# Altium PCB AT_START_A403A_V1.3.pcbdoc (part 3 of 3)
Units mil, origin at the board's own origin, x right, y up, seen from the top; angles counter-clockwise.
Board outline 6370 x 3956 mil, 2 copper layers (Top Layer, Bottom Layer); 182 components, 198 nets, 768 pads, 894 vias.
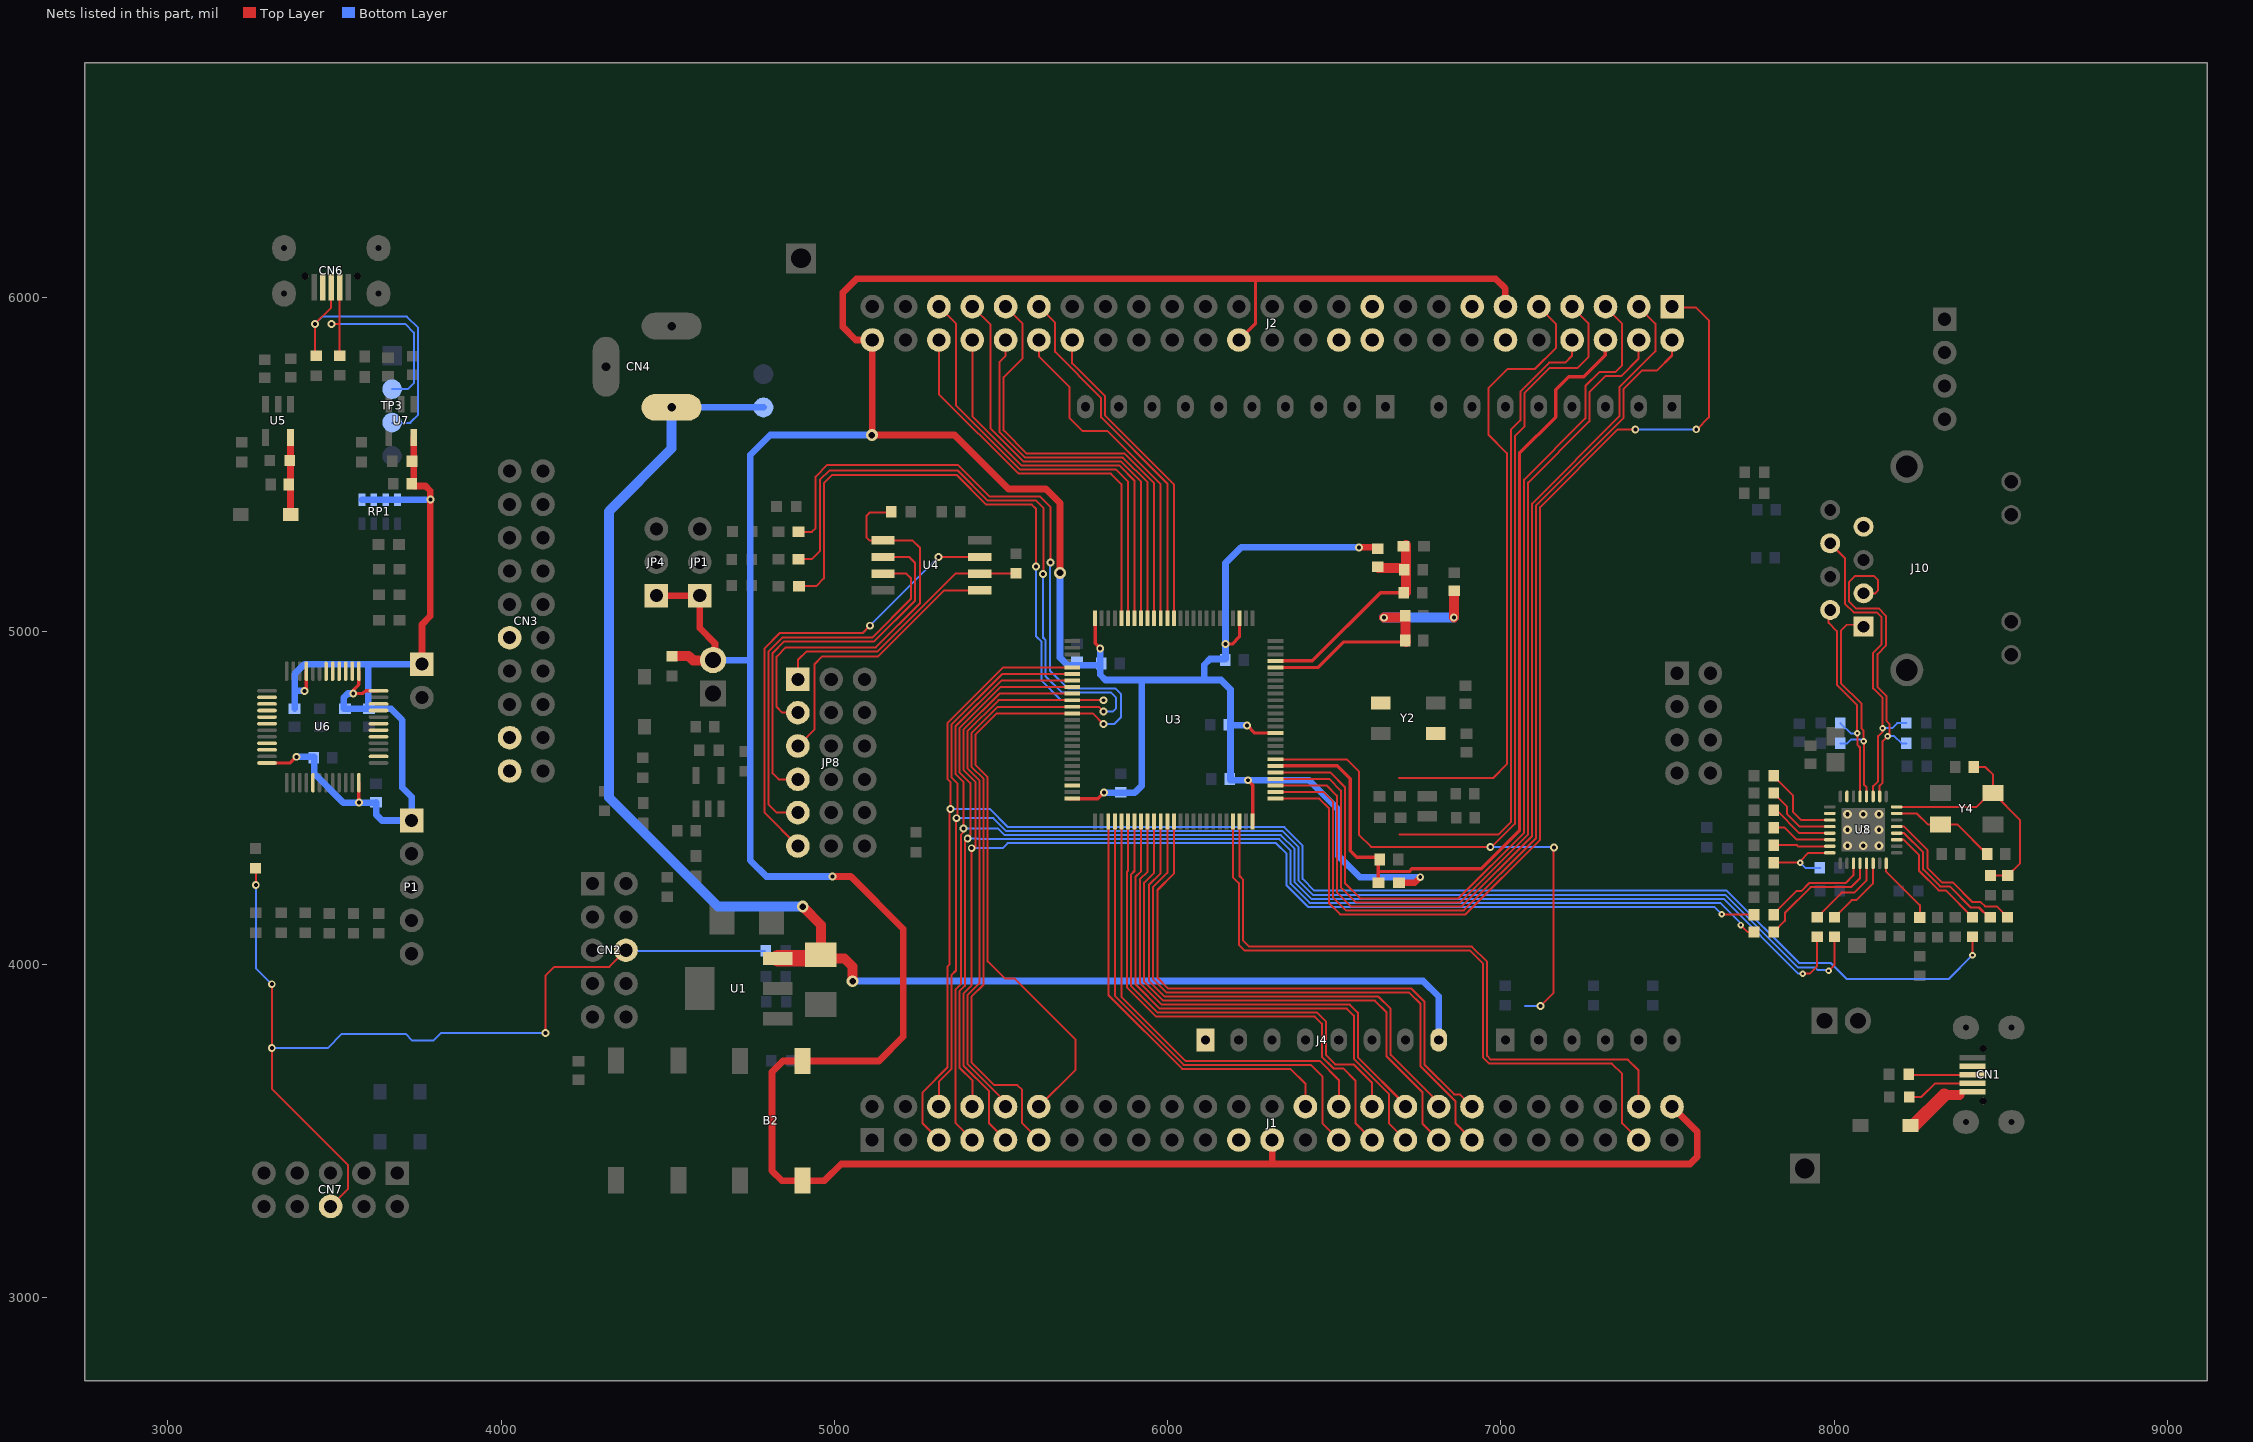
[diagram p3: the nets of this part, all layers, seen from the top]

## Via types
v1: diameter 19.68, hole 7.87, Top Layer to Bottom Layer, 702 vias
v2: diameter 23.62, hole 11.81, Top Layer to Bottom Layer, 166 vias
v3: diameter 35.43, hole 19.68, Top Layer to Bottom Layer, 10 vias
v4: diameter 25.98, hole 12.99, Top Layer to Bottom Layer, 9 vias
v5: diameter 27.56, hole 15.75, Top Layer to Bottom Layer, 5 vias
v6: diameter 43.31, hole 21.65, Top Layer to Bottom Layer, 1 vias
v7: diameter 31.5, hole 19.68, Top Layer to Bottom Layer, 1 vias

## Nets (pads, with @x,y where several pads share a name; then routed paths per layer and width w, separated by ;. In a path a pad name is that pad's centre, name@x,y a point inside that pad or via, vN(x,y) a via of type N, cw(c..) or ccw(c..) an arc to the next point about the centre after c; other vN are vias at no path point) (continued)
PC10: J1.28 U3.78 | length 1290.5
  Top Layer w6: U3.78@5821.76,4428.38 5821.76,3908.05 6043.29,3686.53 6368.23,3686.53 6413.71,3641.05 J1.28@6413.71,3573.46
PC11: J1.29 U3.79 | length 1456.5
  Top Layer w6: U3.79@5841.45,4428.38 5841.45,3905.34 6048.26,3698.53 6429.23,3698.53 6464.06,3663.7 6464.06,3523.11 J1.29@6513.71,3473.46
PC12: J1.30 U3.80 | length 1361.3
  Top Layer w6: U3.80@5861.13,4428.38 5861.13,3902.62 6053.23,3710.53 6456.23,3710.53 6513.71,3653.05 J1.30@6513.71,3573.46
PC13: J2.7 U3.7 | length 3410.1
  Top Layer w6: U3.7@6323.73,4615.39 6537.37,4615.39 6573.58,4579.18 6573.58,4389.18 6610.49,4352.27 v2(6968.03,4352.27) 6972.12,4352.27 7041.54,4421.7 7041.54,5585.09 7069.95,5613.5 7069.95,5713.62 7145.83,5789.5 7229.89,5789.5 7262.58,5822.18 7262.58,5923.74 J2.7@7213.28,5973.03 ; v2(7118.95,3875.18) 7157.95,3914.18 7157.95,4349.5 v2(7158.95,4350.5)
  Bottom Layer w6: v2(6968.03,4352.27) 7157.18,4352.27 v2(7158.95,4350.5) ; 7071.94,3874.89 7118.66,3874.89 v2(7118.95,3875.18)
PC14: J2.8 | length 1900.6
  Top Layer w6: 6695.05,4389.16 6992.03,4389.16 7029.54,4426.67 7029.54,5604.09 7057.95,5632.5 7057.95,5718.59 7144.86,5805.5 7192.89,5805.5 7213.28,5825.89 J2.8@7213.28,5873.03
PC15: J2.9 | length 1888.9
  Top Layer w6: 6694.58,4559.18 6976.28,4559.18 7017.54,4600.44 7017.54,5534.22 6961.95,5589.81 6961.95,5728.18 7020.27,5786.5 7102.27,5786.5 7164.58,5848.81 7164.58,5921.74 J2.9@7113.28,5973.03
PD0: J1.31 U3.81 | length 1557
  Top Layer w6: U3.81@5880.82,4428.38 5880.82,4280.43 5877.58,4277.18 5877.58,3931.1 5965.49,3843.18 6441.58,3843.18 6462.58,3822.18 6462.58,3723.21 6497.61,3688.18 6526.58,3688.18 6563.58,3651.18 6563.58,3523.59 J1.31@6613.71,3473.46
PD1: J1.32 U3.82 | length 1471.7
  Top Layer w6: U3.82@5900.5,4428.38 5900.5,4280.11 5889.58,4269.18 5889.58,3936.07 5970.46,3855.18 6448.58,3855.18 6474.58,3829.18 6474.58,3728.18 6502.58,3700.18 6557.61,3700.18 6613.71,3644.08 J1.32@6613.71,3573.46
PD2: J1.33 U3.83 | length 1625.9
  Top Layer w6: U3.83@5920.19,4428.38 5920.19,4279.21 5903.58,4262.59 5903.58,3940.33 5976.72,3867.18 6537.58,3867.18 6558.58,3846.18 6558.58,3716.18 6663.58,3611.18 6663.58,3523.59 J1.33@6713.71,3473.46
PD3: J1.34 U3.84 | length 1525.7
  Top Layer w6: U3.84@5939.88,4428.38 5939.87,4278.48 5916.58,4255.18 5916.58,3944.3 5981.69,3879.18 6546.58,3879.18 6570.58,3855.18 6570.58,3721.15 6713.71,3578.02 J1.34@6713.71,3573.46
PD4: J1.35 U3.85 | length 1705.7
  Top Layer w6: U3.85@5959.56,4428.38 5959.56,4275.17 5929.58,4245.18 5929.58,3948.27 5986.66,3891.18 6621.58,3891.18 6657.2,3855.56 6657.2,3723.56 6764.58,3616.18 6764.58,3521.74 J1.35@6813.28,3473.03
PD5: J1.36 U3.86 | length 1605.8
  Top Layer w6: U3.86@5979.25,4428.38 5979.24,4273.85 5943.58,4238.18 5943.58,3951.24 5991.63,3903.18 6632.58,3903.18 6669.2,3866.56 6669.2,3728.53 6813.28,3584.45 J1.36@6813.28,3573.03
PD6: J1.37 U3.87 | length 1796.4
  Top Layer w6: U3.87@5998.93,4428.38 5998.93,4274.54 5955.58,4231.18 5955.58,3956.21 5996.61,3915.18 6724.58,3915.18 6758.58,3881.18 6758.58,3694.21 6863.58,3589.21 6863.58,3522.74 J1.37@6913.28,3473.03
PD7: J1.38 U3.88 | length 1703.9
  Top Layer w6: U3.88@6018.62,4428.38 6018.62,4272.22 5969.58,4223.18 5969.58,3959.18 6001.58,3927.18 6731.58,3927.18 6770.58,3888.18 6770.58,3699.18 6859.8,3609.96 6876.35,3609.96 J1.38@6913.28,3573.03
PD8: J1.5 R86.1 U3.55 | length 5174.5
  Top Layer w6: J1.5@5313.71,3473.46 5264.58,3522.59 5264.58,3616.18 5338.95,3690.56 5338.95,3993.31 5346.14,4000.5 5346.14,4464.69 v2(5347.95,4466.5) 5347.95,4547.53 5338.95,4556.53 5338.95,4723.69 5506.24,4890.98 U3.55@5713.5,4890.98 ; v1(8415,4027) R86.1@8415,4082.34
  Bottom Layer w6: v2(5347.95,4466.5) 5465.95,4466.5 5520.95,4411.5 6349.89,4411.5 6404.95,4356.44 6404.95,4256.44 6439.89,4221.5 7677.09,4221.5 7894.59,4004 7990,4004 8038,3956 8343,3956 8414,4027 v1(8415,4027)
PD9: J1.6 R82.1 U3.56 | length 4583.3
  Top Layer w6: J1.6@5313.71,3573.46 5313.71,3648.25 5350.95,3685.5 5350.95,3967.5 5364.95,3981.5 v2@5364.95,4436.5 ; v2@5366.95,4433.5 5369.95,4430.5 5369.95,4542.5 5350.95,4561.5 5350.95,4718.72 5503.52,4871.29 U3.56@5713.5,4871.29 ; v1(7983,3981) 8001,3999 R82.1@8001,4082.34
  Bottom Layer w6: v2(5366.95,4438.5) 5476.98,4438.5 5515.98,4399.5 6344.92,4399.5 6392.95,4351.47 6392.95,4251.47 6435.92,4208.5 7673.12,4208.5 7890.78,3990.84 7942.58,3990.84 7950.61,3982.81 7981.19,3982.81 v1(7983,3981)
PD10: J1.7 R81.1 U3.57 | length 4588.1
  Top Layer w6: J1.7@5413.71,3473.46 5362.95,3524.21 5362.95,3924.21 5379.2,3940.46 5379.2,4389.09 5386.95,4396.85 v2(5386.95,4407.78) 5387.76,4408.6 5387.76,4546.72 5362.95,4571.53 5362.95,4713.75 5500.81,4851.61 U3.57@5713.5,4851.61 ; v1(7906,3972) 7927,3972 7949,3994 R81.1@7949,4082.34
  Bottom Layer w6: v2(5386.95,4407.78) 5490.73,4407.78 5511.01,4387.5 6339.95,4387.5 6380.95,4346.5 6380.95,4246.5 6430.95,4196.5 7668.15,4196.5 7892.65,3972 v1(7906,3972)
PD11: J1.8 R80.2 U3.58 | length 4106
  Top Layer w6: J1.8@5414.15,3573.9 5413.71,3573.46 5413.71,3651.75 5374.95,3690.5 5374.95,3919.24 5391.2,3935.48 5391.2,4369.31 v2(5400.01,4378.12) 5407.76,4385.88 5407.76,4543.69 5374.95,4576.5 5374.95,4708.78 5498.1,4831.92 U3.58@5713.5,4831.92 ; v1(7720,4118) 7741,4097 R80.2@7759.34,4097
  Bottom Layer w6: v2(5400.01,4378.12) 5428.95,4378.12 5431.58,4375.5 6334.98,4375.5 6368.95,4341.53 6368.95,4241.53 6425.98,4184.5 7658.5,4184.5 7720,4123 v1(7720,4118)
PD12: J1.9 R79.2 U3.59 | length 4177
  Top Layer w6: v2(5412.03,4348.5) 5412.03,3937.52 5386.95,3912.44 5386.95,3696.5 5464.58,3618.88 5464.58,3522.59 J1.9@5513.71,3473.46 ; 5424.03,4349.58 5424.03,4546.51 5386.95,4583.59 5386.95,4703.81 5495.38,4812.24 U3.59@5713.5,4812.24 ; v1(7662,4150) 7663,4149 R79.2@7759.34,4149
  Bottom Layer w6: v2(5412.03,4348.5) 5504.95,4348.5 5519.95,4363.5 6324.98,4363.5 6356.95,4331.53 6356.95,4236.56 6421.01,4172.5 7639.5,4172.5 v1(7662,4150)
PD13: J1.10 LED2.2 U3.60 | length 3442.7
  Top Layer w6: LED2.2@4893.58,5134.81 4945.21,5134.81 4968.58,5158.18 4968.58,5443.5 4993.58,5468.5 5366.35,5468.5 5455.66,5379.18 5592.27,5379.18 5604.95,5366.5 v2(5604.95,5193.5) ; J1.10@5513.71,3573.46 5513.71,3586.75 5398.95,3701.5 5398.95,3907.47 5436.03,3944.55 5436.03,4551.48 5398.95,4588.56 5398.95,4698.84 5492.67,4792.55 U3.60@5713.5,4792.55 v2(5807.58,4792.55)
  Bottom Layer w6: v2(5604.95,5193.5) 5604.95,4984.78 5621.95,4967.78 5621.95,4850.55 5679.95,4792.55 v2(5807.58,4792.55)
PD14: J1.11 LED3.2 U3.61 | length 3648.2
  Top Layer w6: LED3.2@4892.91,5215.59 4932.32,5215.59 4956.58,5239.85 4956.58,5453.5 4985.58,5482.5 5369.32,5482.5 5460.63,5391.18 5605.27,5391.18 5626.95,5369.5 5626.95,5173.5 v2@5625.95,5172.5 ; J1.11@5613.71,3473.46 5563.58,3523.59 5563.58,3623.18 5549.26,3637.5 5479.92,3637.5 5410.95,3706.47 5410.95,3902.5 5448.03,3939.58 5448.03,4556.45 5410.95,4593.53 5410.95,4693.87 5489.95,4772.87 5656.95,4772.87 U3.61@5713.5,4772.87 5792.89,4772.87 v2(5807.58,4758.18)
  Bottom Layer w6: v2(5625.95,5171.5) 5625.95,4980.75 5633.95,4972.75 5633.95,4863.81 5681.58,4816.18 5829.58,4816.18 5845.58,4800.18 5845.58,4768.18 5835.58,4758.18 v2(5807.58,4758.18)
PD15: J1.12 LED4.2 U3.62 | length 3572.5
  Top Layer w6: LED4.2@4892.58,5297.81 4932.54,5297.81 4943.91,5309.18 4943.91,5463.5 4978.91,5498.5 5370.29,5498.5 5465.61,5403.18 5617.27,5403.18 5647.95,5372.5 v2(5647.95,5205.5) ; J1.12@5613.71,3573.46 5723.58,3683.33 5723.58,3774.45 5540.34,3957.69 5511.39,3957.69 5460.03,4009.05 5460.03,4561.42 5422.95,4598.5 5422.95,4688.9 5487.24,4753.18 5665.95,4753.18 U3.62@5713.5,4753.18 5774.61,4753.18 5806.61,4721.18 v2(5807.58,4721.18)
  Bottom Layer w6: v2(5647.95,5205.5) 5646.76,5204.31 5646.76,4881.69 5700.27,4828.18 5842.72,4828.18 5860.58,4810.33 5860.58,4742.18 5839.58,4721.18 v2(5807.58,4721.18)
PE0: J1.47 U3.97 | length 2071.2
  Top Layer w6: U3.97@6195.78,4428.38 6195.78,4261.18 6213.58,4243.39 6213.58,4059.18 6231.58,4041.18 6907.61,4041.18 6946.58,4002.21 6946.58,3720.21 6964.61,3702.18 7332.58,3702.18 7363.58,3671.18 7363.58,3522.74 J1.47@7413.28,3473.03
PE1: J1.48 U3.98 | length 1983.6
  Top Layer w6: U3.98@6215.47,4428.38 6215.47,4265.18 6225.58,4255.07 6225.58,4072.18 6244.58,4053.18 6912.58,4053.18 6958.58,4007.18 6958.58,3725.18 6969.58,3714.18 7380.58,3714.18 7413.28,3681.48 J1.48@7413.28,3573.03
PE2: J2.1 U3.1 | length 3232.8
  Top Layer w6: U3.1@6323.73,4497.28 6455.48,4497.28 6483.58,4469.18 6483.58,4184.18 6517.58,4150.18 6893.64,4150.18 7117.54,4374.09 7117.54,5372.15 7350.89,5605.5 7351.08,5605.31 v2(7403.14,5605.31) ; J2.1@7513.28,5973.03 7515.82,5970.5 7585.95,5970.5 7623.95,5932.5 7623.95,5641.5 v2@7586.95,5604.5
  Bottom Layer w6: v2(7403.14,5605.31) 7585.76,5605.31 v2(7585.95,5605.5) v2@7586.95,5606.5
PE3: J2.2 U3.2 | length 2876.5
  Top Layer w6: U3.2@6323.73,4516.96 6467.8,4516.96 6495.58,4489.18 6495.58,4201.18 6534.58,4162.18 6888.64,4162.18 7105.54,4379.09 7105.54,5377.12 7367.58,5639.15 7367.58,5726.21 7423.86,5782.5 7468.89,5782.5 7513.28,5826.89 J2.2@7513.28,5873.03
PE4: J2.3 U3.3 | length 2939.2
  Top Layer w6: U3.3@6323.73,4536.65 6477.11,4536.65 6507.58,4506.18 6507.58,4216.18 6549.58,4174.18 6882.64,4174.18 7093.54,4385.09 7093.54,5382.09 7355.58,5644.12 7355.58,5731.18 7463.58,5839.18 7463.58,5922.74 J2.3@7413.28,5973.03
PE5: J2.4 U3.4 | length 2813.3
  Top Layer w6: U3.4@6323.73,4556.33 6484.43,4556.33 6519.58,4521.18 6519.58,4231.18 6564.58,4186.18 6877.67,4186.18 7081.54,4390.06 7081.54,5445.09 7265.58,5629.12 7265.58,5717.12 7313.64,5765.18 7360.58,5765.18 7413.28,5817.89 J2.4@7413.28,5873.03
PE6: J2.5 U3.5 | length 2900.8
  Top Layer w6: U3.5@6323.73,4576.02 6487.74,4576.02 6531.58,4532.18 6531.58,4244.18 6577.58,4198.18 6872.7,4198.18 7069.54,4395.03 7069.54,5454.09 7253.58,5638.12 7253.58,5735.39 7295.37,5777.18 7342.58,5777.18 7363.58,5798.18 7363.58,5922.74 J2.5@7313.28,5973.03
PE7: J2.38 U3.38 | length 961.1
  Top Layer w6: J2.38@5713.71,5873.46 5713.71,5803.11 5812.58,5704.24 5812.58,5646.18 6018.62,5440.14 U3.38@6018.62,5038.62
PE8: J2.39 U3.39 | length 1094.4
  Top Layer w6: J2.39@5613.71,5973.46 5662.21,5924.95 5662.21,5837.63 5800.58,5699.26 5800.58,5641.21 5998.93,5442.86 U3.39@5998.93,5038.62
PE9: J2.40 U3.40 | length 1030.2
  Top Layer w6: J2.40@5613.71,5873.46 5613.71,5824.05 5705.95,5731.81 5705.95,5638.81 5744.58,5600.18 5819.58,5600.18 5979.24,5440.51 U3.40@5979.25,5038.62
PE10: J2.41 U3.41 | length 1338.4
  Top Layer w6: J2.41@5513.71,5973.46 5564.58,5922.59 5564.58,5819.18 5507.58,5762.18 5507.58,5602.18 5577.58,5532.18 5870.61,5532.18 5959.56,5443.23 5959.56,5110.5 U3.41@5959.56,5038.62
PE11: J2.42 U3.42 | length 1198
  Top Layer w6: J2.42@5513.71,5873.46 5513.71,5826.18 5495.58,5808.05 5495.58,5597.21 5572.61,5520.18 5865.63,5520.18 5939.87,5445.94 5939.87,5109.18 ; U3.42@5939.88,5038.62 5939.88,5109.18
PE12: J2.43 U3.43 | length 1316.3
  Top Layer w6: J2.43@5413.71,5973.46 5468.58,5918.59 5468.58,5607.24 5567.63,5508.18 5860.66,5508.18 5920.19,5448.66 5920.19,5114.5 U3.43@5920.19,5038.62
PE13: J2.44 U3.44 | length 1208.1
  Top Layer w6: J2.44@5413.71,5873.46 5413.71,5645.14 5562.66,5496.18 5855.69,5496.18 5900.5,5451.37 5900.5,5128.5 U3.44@5900.5,5038.62
PE14: J2.45 U3.45 | length 1338.4
  Top Layer w6: J2.45@5313.71,5973.46 5365.58,5921.59 5365.58,5676.3 5557.69,5484.18 5845.58,5484.18 5880.82,5448.94 5880.82,5128.5 U3.45@5880.82,5038.62
PE15: J2.46 U3.46 | length 1223.8
  Top Layer w6: J2.46@5313.71,5873.46 5313.71,5711.2 5552.72,5472.18 5829.58,5472.18 5861.13,5440.62 5861.13,5144.5 U3.46@5861.13,5038.62
PHY_RST: R63.1 U8.29 | length 476.6
  Top Layer w6: U8.29@8187.6,4413.34 8209.66,4413.34 8280,4343 8280,4289 8323,4246 8356,4246 8415,4187 8439.63,4187 8452.63,4174 8487.66,4174 R63.1@8520,4141.66
RX+: J10.3 R58.2 U8.2 | length 1011.2
  Top Layer w6: J10.3@8088.04,5113.3 8123.3,5113.3 8132.06,5122.06 8132.06,5151.94 8118,5166 8063,5166 8044,5147 8044,5089 8065,5068 8133,5068 8155,5046 8155,4956.03 8130,4931.03 8130,4831.91 8157,4804.91 8157,4729.7 8166,4720.7 8166,4690.96 v1(8160,4684.96) 8145,4669.96 8145,4545 8136.42,4536.42 U8.2@8136.42,4503.89
  Bottom Layer w6: v1(8160,4684.96) 8180.04,4684.96 8202,4663 R58.2@8216.34,4663
RX-: J10.6 R59.2 U8.3 | length 975.6
  Top Layer w6: J10.6@7988.04,5263.3 8032,5219.34 8032,5082 8058,5056 8128,5056 8142,5042 8142,4960 8116.73,4934.73 8116.73,4828.2 8145,4799.94 v1(8145,4709) 8145,4698 8132,4685 8132,4550 8116.73,4534.73 U8.3@8116.73,4503.89
  Bottom Layer w6: v1(8145,4709) 8174,4709 8189,4724 R59.2@8216.34,4724
RXCLK: R83.2 U8.24 | length 204.2
  Top Layer w6: U8.24@8156.1,4303.1 8156.1,4278.35 8257,4177.45 R83.2@8257,4140.66
RXD0: R82.2 U8.22 | length 217.3
  Top Layer w6: R82.2@8001,4141.66 8052.34,4193 8065.83,4193 8116.73,4243.91 U8.22@8116.73,4303.1
RXD1: R81.2 U8.21 | length 244.8
  Top Layer w6: R81.2@7949,4141.66 8022.34,4215 8060,4215 8097.05,4252.05 U8.21@8097.05,4303.1
RXD2: R80.1 U8.20 | length 384.2
  Top Layer w6: R80.1@7818.66,4097 7852,4130.34 7852,4154.17 7929.33,4231.5 8050.36,4231.5 8077.36,4258.5 U8.20@8077.36,4303.1
RXD3: R79.1 U8.19 | length 325.3
  Top Layer w6: R79.1@7818.66,4149 7818.66,4151.66 7886.61,4219.61 7900.47,4219.61 7924.36,4243.5 8033.81,4243.5 8057.68,4267.37 U8.19@8057.68,4303.1
RXDV: R86.2 U8.27 | length 351.1
  Top Layer w6: U8.27@8187.6,4373.97 8208.03,4373.97 8255,4327 8255,4280.06 8313.06,4222 8334.66,4222 R86.2@8415,4141.66
RXER: R62.2 U8.28 | length 414.6
  Top Layer w6: U8.28@8187.6,4393.66 8209.34,4393.66 8267,4336 8267,4285.03 8318.03,4234 8346.61,4234 8410.09,4170.53 8434.47,4170.53 8463.34,4141.66 R62.2@8468,4141.66
SPIM_IO0: JP8.7 U4.5 | length 853.8
  Top Layer w6: JP8.7@4890.58,4655.18 4940.58,4705.18 4940.58,4901.18 4962.58,4923.18 5130.52,4923.18 5329.83,5122.5 U4.5@5435.95,5122.5
SPIM_IO1: JP8.10 U4.2 | length 1153.4
  Top Layer w6: JP8.10@4890.58,4555.18 4832.58,4555.18 4814.58,4573.18 4814.58,4934.18 4849.58,4969.18 5119.58,4969.18 5241.95,5091.56 5241.95,5204.5 5223.95,5222.5 U4.2@5145.95,5222.5
SPIM_IO2: JP8.13 U4.3 | length 1202.2
  Top Layer w6: JP8.13@4890.58,4455.18 4826.58,4455.18 4802.58,4479.18 4802.58,4939.15 4844.61,4981.18 5114.61,4981.18 5229.95,5096.53 5229.95,5158.5 5215.95,5172.5 U4.3@5145.95,5172.5
SPIM_IO3: JP8.16 U4.7 | length 1393.4
  Top Layer w6: JP8.16@4890.58,4355.18 4790.58,4455.18 4790.58,4948.18 4836.58,4994.18 5084.58,4994.18 v2(5106.58,5016.18) ; v2(5312.89,5222.5) U4.7@5435.95,5222.5
  Bottom Layer w6: v2(5106.58,5016.18) v2(5312.89,5222.5)
SPIM_NSS: JP8.4 R11.2 U4.1 | length 1201.3
  Top Layer w6: JP8.4@4890.58,4755.18 4843.58,4755.18 4826.58,4772.18 4826.58,4923.18 4854.58,4951.18 5124.58,4951.18 5256.95,5083.56 5256.95,5249.5 5233.95,5272.5 U4.1@5145.95,5272.5 5104.95,5272.5 5096.95,5280.5 5096.95,5346.5 5106.84,5356.39 R11.2@5170.54,5356.39
SPIM_SCK: JP8.1 R12.2 U4.6 | length 819.8
  Top Layer w6: JP8.1@4890.58,4855.18 4890.58,4913.18 4916.58,4939.18 5129.55,4939.18 5362.86,5172.5 U4.6@5435.95,5172.5 R12.2@5544.95,5172.5
SWO: CN2.6 CN7.6 R4.2 R42.2 | length 2875
  Top Layer w6: v2(3263.95,4238.5) R42.2@3263.95,4292.5 ; v2(3311.95,3940.5) v2(3311.95,3748.5) 3311.95,3626.5 3539.95,3398.5 3539.95,3325.31 CN7.6@3488.43,3273.78 ; v2(4132.95,3793.5) 4132.95,3965.5 4159.95,3992.5 4324.89,3992.5 CN2.6@4374.58,4042.18
  Bottom Layer w6: v2(3263.95,4238.5) 3263.95,3988.5 v2(3311.95,3940.5) ; v2(3311.95,3748.5) 3479.49,3748.5 3522.49,3791.5 3713.52,3791.5 3733.98,3771.04 3796.92,3771.04 3819.39,3793.5 v2(4132.95,3793.5) ; CN2.6@4374.58,4042.18 4376.27,4040.49 R4.2@4792.49,4040.49
TX+: J10.1 R56.2 U8.4 | length 682.8
  Top Layer w6: J10.1@8088.04,5013.3 8082.34,5019 8038,5019 8020,5001 8020,4843.97 8082,4781.97 8082,4707 8088,4701 v1(8088,4669) 8088,4666 8089.36,4664.64 8089.36,4538.64 8097.05,4530.95 U8.4@8097.05,4503.89
  Bottom Layer w6: R56.2@8018.66,4663 8039,4663 8050,4674 8083,4674 v1(8088,4669)
TX-: J10.2 R57.2 U8.5 | length 663.8
  Top Layer w6: J10.2@7988.04,5063.3 7983,5058.26 7983,5025 8008,5000 8008,4839 8069,4778 v1(8069,4693) 8069.16,4692.84 8069.16,4658.84 8077.36,4650.64 U8.5@8077.36,4503.89
  Bottom Layer w6: R57.2@8018.66,4724 8049.66,4693 v1(8069,4693)
TXCLK: R66.2 R76.1 U8.16 | length 251.2
  Top Layer w6: R76.1@7820.42,4300.5 7824.98,4305.05 v1@7897.95,4305.05 ; v1(7898,4305) 7898,4310 7922.6,4334.6 U8.16@7986.81,4334.6
  Bottom Layer w6: v1(7898,4305) 7914.5,4288.5 R66.2@7958.95,4288.5
TXD0: R74.1 U8.14 | length 183.1
  Top Layer w6: R74.1@7818.66,4410 7851,4410 7887.03,4373.97 U8.14@7986.81,4373.97
TXD1: R73.1 U8.13 | length 196.4
  Top Layer w6: R73.1@7818.66,4462 7827.16,4461.99 7895.49,4393.66 U8.13@7986.81,4393.66
TXD2: R72.1 U8.12 | length 223.1
  Top Layer w6: R72.1@7818.66,4514 7818.66,4513.34 7858,4474 7858,4452 7896.66,4413.34 U8.12@7986.81,4413.34
TXD3: R71.1 U8.11 | length 252.9
  Top Layer w6: R71.1@7818.66,4566 7818.66,4564.34 7876,4507 7876,4458 7900.97,4433.03 U8.11@7986.81,4433.03
TXEN: R75.1 U8.15 | length 168.1
  Top Layer w6: R75.1@7820.44,4358.52 7886.9,4358.52 7891.13,4354.29 U8.15@7986.81,4354.29
USB_M: CN1.2 R22.2 | length 205.4
  Top Layer w6: R22.2@8225.95,3602.5 8261.95,3602.5 8302.62,3643.17 CN1.2@8414.55,3643.17
USB_P: CN1.3 R20.2 | length 188.6
  Top Layer w6: R20.2@8225.95,3668.76 CN1.3@8414.55,3668.76
USBM: CN6.2 R38.2 TP3.2 | length 715.5
  Top Layer w6: v2(3491.01,5921.78) 3515.8,5921.78 ; R38.2@3515.28,5823.78 3515.8,5824.3 3515.8,5921.78 ; CN6.2@3515.95,6032.02 3515.8,6031.87 3515.8,5921.78
  Bottom Layer w6: v2(3491.01,5921.78) 3712.01,5921.78 3738.01,5895.78 3738.01,5743.78 3720.01,5725.78 TP3.2@3673.01,5725.78
USBP: CN6.3 R37.2 TP3.3 | length 910.9
  Top Layer w6: R37.2@3441.43,5822.67 v2(3441.43,5921.78) 3490.21,5970.56 3490.21,6031.87 CN6.3@3490.36,6032.02
  Bottom Layer w6: v2(3441.43,5921.78) 3463.43,5943.78 3717.01,5943.78 3751.01,5909.78 3751.01,5648.78 3728.01,5625.78 ; TP3.3@3673.01,5623.71 3728.01,5623.71
VBAT: CB4.2 J2.6 R15.2 U3.6 | length 2696.9
  Top Layer w10: U3.6@6323.73,4595.7 6509.06,4595.7 6547.58,4557.18 6547.58,4341.18 6567.14,4321.62 6631.63,4321.62 6631.63,4278.57 ; R15.2@6631.63,4252.53 6631.63,4278.57 ; J2.6@7313.28,5873.03 7313.28,5827.89 7248.11,5762.71 7203.17,5762.71 7164.58,5724.12 7164.58,5642.12 7055.54,5533.09 7055.54,4400.83 6941.21,4286.5 6732.51,4286.5 6724.58,4278.57 6631.63,4278.57
VBUS: CN1.1 D1.1 | length 184.7
  Top Layer w30: 8329.95,3607.5 8375.95,3607.5
  Top Layer w40: D1.1@8228.95,3516.5 8238.95,3516.5 8329.95,3607.5
VCC: C8.2 C9.2 C10.2 C11.2 C12.2 C14.2 J9.1 P1.1 R43.1 RP1.5 RP1.6 RP1.7 RP1.8 U6.1 U6.9 U6.24 U6.36 U6.48 U7.5 | length 3016.8
  Top Layer w10: U6.24@3297.58,4604.19 3367.36,4604.19 v2(3385.95,4622.78) ; v2(3410.43,4819.78) 3415.69,4825.04 U6.9@3415.69,4879.78 ; v2@3573.17,4485.58 U6.36@3573.17,4545.14 ; U6.1@3573.17,4879.78 3573.17,4839.52 3556.43,4822.78 v2(3556.43,4812.78) 3585.43,4812.78 3593.38,4820.73 U6.48@3632.22,4820.73
  Top Layer w20: U7.5@3737.43,5580.6 3737.43,5435.89 3737.05,5435.51 3772.95,5435.51 3787.43,5421.02 3787.43,5044.78 3762.43,5019.78 J9.1@3762.43,4900.78
  Bottom Layer w20: C12.2@3380.43,4766.78 3380.43,4820.78 ; v2(3385.95,4622.78) 3439.18,4622.78 3439.18,4572.17 3525.95,4485.4 v2(3573.35,4485.4) C11.2@3624.89,4485.4 ; v2(3410.43,4819.78) 3409.43,4820.78 3380.43,4820.78 ; v2(3556.43,4812.78) 3540.43,4812.78 3527.43,4799.78 3527.43,4766.78 C8.2@3601.43,4766.78 ; RP1.8@3582.52,5394.5 RP1.7@3617.95,5394.5 RP1.6@3653.39,5394.5 RP1.5@3688.82,5394.5 v2(3787.95,5394.5) ; C11.2@3625.01,4485.52 3625.01,4449.28 3642.51,4431.78 P1.1@3731.43,4431.78 3731.43,4502.78 3703.43,4530.78 3703.43,4732.78 3669.43,4766.78 C8.2@3601.43,4766.78 ; J9.1@3762.43,4900.78 3601.43,4900.78 ; 3380.43,4820.78 3380.43,4870.78 3410.43,4900.78 3601.43,4900.78 ; C8.2@3601.43,4766.78 3601.43,4900.78
VCC3.5V: C17.2 D5.1 R50.1 U5.5 | length 231.2
  Top Layer w20: U5.5@3368.23,5580.67 3368.23,5350.57 D5.1@3369.01,5349.78
VDD: B2.1 CB10.2 CB11.2 CB12.2 CB13.2 CB14.2 CT3.2 J1.25 J1.50 J2.11 J2.28 J2.50 JP1.1 JP3.2 JP4.1 L3.1 R13.2 R15.1 U3.11 U3.28 U3.50 U3.75 U3.100 | length 14437
  Top Layer w10: 5613.71,6056.31 5614.58,6057.18 ; U3.75@5703.65,4497.28 5790.67,4497.28 v2(5808.58,4515.18) ; U3.50@5782.39,5048.46 5782.39,4963.36 v2(5797.58,4948.18) ; v2(6173.58,4961.18) 6194.37,4961.18 6215.47,4982.28 U3.28@6215.47,5048.46 ; J2.28@6213.28,5873.03 J2.28@6213.71,5873.46 6263.58,5923.33 6263.58,6057.18 ; v2(6238.58,4717.18) 6261.63,4694.13 U3.11@6333.58,4694.13 ; v2(6240.58,4552.39) 6254.84,4538.13 U3.100@6254.84,4418.54
  Top Layer w20: JP4.1@4465.95,5106.5 JP1.1@4595.95,5106.5 4595.95,5008.81 4641.58,4963.18 JP3.2@4641.58,4912.21 ; v2(4993.95,4263.5) 5049.45,4263.5 5206.65,4106.3 5206.65,3783.2 5133.64,3710.18 B2.1@4904.58,3710.18 4845.98,3710.18 4812.95,3677.16 4812.95,3380.5 4842.27,3351.18 B2.1@4904.58,3351.18 4970.58,3351.18 5020.58,3401.18 6312.58,3401.18 ; 5064.58,6055.18 5025.58,6016.18 5025.58,5912.18 5064.3,5873.46 J2.50@5113.71,5873.46 5113.71,5589.31 v3(5112.58,5588.18) 5360.58,5588.18 5522.58,5426.18 5634.95,5426.18 5676.95,5384.18 v3(5676.95,5174.5) ; 5066.58,6057.18 5614.58,6057.18 6263.58,6057.18 6983.58,6057.18 7013.28,6027.48 J2.11@7013.28,5973.03 ; J1.25@6313.71,3473.46 6313.71,3402.31 6312.58,3401.18 ; v2(6574.58,5251.18) 6631.53,5251.18 L3.1@6632.12,5250.59 ; R15.1@6687.07,4245 6741.45,4245 v2(6757.95,4261.5) ; J1.50@7513.28,3573.03 7589.42,3496.89 7589.42,3423.03 7567.58,3401.18 6312.58,3401.18
  Top Layer w30: R13.2@4514.51,4925.5 4562.95,4925.5 4576.24,4912.21 JP3.2@4641.58,4912.21
  Bottom Layer w20: JP3.2@4641.58,4912.21 4747.58,4912.21 ; v2(4993.95,4263.5) 4796,4263.5 4747.58,4311.92 4747.58,4912.21 ; v3(5112.58,5588.18) 4807.58,5588.18 4747.58,5528.18 4747.58,4912.21 ; v3(5676.95,5174.5) 5676.95,4920.42 5700.19,4897.18 CB12.2@5797.58,4897.18 ; v2(5797.58,4948.18) CB12.2@5797.58,4897.18 ; v2(5808.58,4515.18) 5901.54,4515.14 5922.58,4536.18 5922.58,4852.18 5923.58,4853.18 ; CB14.2@6188.58,4717.35 6188.62,4552.39 v2(6240.58,4552.39) 6424.61,4552.39 6511.58,4465.42 6511.58,4326.88 6576.95,4261.5 v2(6757.95,4261.5) ; v2(6238.58,4717.18) 6238.37,4717.39 6188.62,4717.39 6188.62,4825.14 6160.58,4853.18 6109.58,4853.18 ; v2(6574.58,5251.18) 6220.58,5251.18 6173.58,5204.18 v2(6173.58,4961.18) 6173.58,4916.18 6126.58,4916.18 6109.58,4899.18 6109.58,4853.18 ; CB12.2@5797.58,4897.18 5797.58,4869.18 5813.58,4853.18 5923.58,4853.18 ; 5923.58,4853.18 6109.58,4853.18
VDDA: CB8.1 CB9.1 L3.2 R17.2 U3.22 | length 701.8
  Top Layer w10: U3.22@6323.73,4910.66 6433.93,4910.66 6638.62,5115.35 CB8.1@6714.95,5115.35
  Top Layer w30: L3.2@6632.12,5189.59 6714.71,5189.59 CB9.1@6714.95,5189.35 ; CB8.1@6714.95,5115.35 CB9.1@6714.95,5189.35 ; R17.2@6714.95,5258.18 CB9.1@6714.95,5189.35
VIN: CN4.1 CT1.1 J4.8 TP1.1 U1.3 | length 4606
  Top Layer w30: v3(4904.95,4173.24) 4959.9,4118.29 CT1.1@4959.9,4018.05 ; CT1.1@4959.95,4018 5029.95,4018 5054.58,3993.38 v3(5054.58,3949.5)
  Top Layer w50: U1.3@4830.08,4018.05 CT1.1@4959.9,4018.05
  Bottom Layer w20: CN4.1@4511.58,5671.18 TP1.1@4787.58,5671.18 ; v3@5054.95,3950.18 6766.58,3950.18 6813.28,3903.48 J4.8@6813.28,3773.03
  Bottom Layer w30: CN4.1@4511.58,5671.18 4511.58,5547.5 4323.58,5359.5 4323.58,4500.62 4650.95,4173.24 v3(4904.95,4173.24)
VREF: CB6.2 CB7.2 L1.2 U3.21 | length 843.7
  Top Layer w10: U3.21@6323.73,4890.98 6452.3,4890.98 6528.71,4967.39 CB7.2@6714.54,4967.39
  Top Layer w30: v2(6649.58,5040.18) 6650.15,5040.76 6713.87,5040.76 6713.87,4968.05 CB7.2@6714.54,4967.39 ; v2(6858.58,5041.18) 6859.12,5041.72 L1.2@6859.12,5114.59
  Bottom Layer w30: v2(6649.58,5040.18) 6650.58,5041.18 v2(6858.58,5041.18)
XT1: C6.1 R39.1 R64.1 U8.32 Y4.1 | length 777.7
  Top Layer w6: U8.32@8187.6,4472.4 8427.4,4472.4 8469.24,4514.24 Y4.1@8476.74,4514.24 ; C6.1@8418.56,4592 8454,4592 8476.74,4569.26 Y4.1@8476.74,4514.24 ; R39.1@8469,4266.66 R64.1@8521,4266.66 8558,4303.66 8558,4432.98 Y4.1@8476.74,4514.24
XT2: C7.1 U8.31 Y4.3 | length 321.3
  Top Layer w6: U8.31@8187.6,4452.71 8248.29,4452.71 8281.24,4419.76 Y4.3@8319.26,4419.76 8369.68,4419.76 C7.1@8458.44,4331
"": CN1.4 CN1.MH1 CN1.MH2 CN3.11 CN3.17 CN3.19 CN6.4 CN6.MH1 CN6.MH2 J1.23 J2.12 J2.13 J2.19 J2.20 J2.22 J4.1 J10.7 U3.73 U6.2 U6.3 U6.4 U6.5 U6.6 U6.14 U6.15 U6.16 U6.17 U6.18 U6.21 U6.22 U6.29 U6.38 U6.41 U6.42 U6.43 U6.45 U6.46 U8.7 U8.10 Y2.2 Y2.4
  other v4: 8039.96,4356.25 8087.21,4356.25 8134.45,4356.25 8039.96,4403.5 8087.21,4403.5 8134.45,4403.5 8039.96,4450.74 8087.21,4450.74 8134.45,4450.74

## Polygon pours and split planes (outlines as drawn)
GND on Top Layer (solid, remove dead copper, pour order 0): 3000,3000 8870,3000 8870,6390 3000,6390
GND on Bottom Layer (solid, remove dead copper, pour order 1): 3059,3154 8725,3154 8725,6456 3059,6456

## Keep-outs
Top Layer:
  region net "": 8136.95,3694.76 8252.07,3694.76 8255.05,3691.78 8255.05,3576.59 8253.95,3575.5 8136.95,3575.5
  region net "": 4173.95,4232.5 4173.95,4146.5 4211.26,4146.5 4215.58,4142.18 4215.58,4233.81 4215.95,4234.18 4172.64,4234.18 4168.95,4230.5
  region net "": 3494.43,4545.14 3494.43,4460.78 3484.43,4450.78 3484.43,4407.78 3514.12,4437.47 3514.12,4545.14
  region net "": 3447.04,4406.78 3483.43,4406.78 3514.12,4437.47 3514.12,4441.1 3494.43,4460.78 3484.43,4450.78 3447.04,4450.78
  region net "": 3460.01,5474.78 3460.01,5940.36 3490.21,5970.56 3517.01,5970.56 3517.01,5725.36 3493.01,5701.36 3493.01,5474.78
Bottom Layer:
  region net "": 3484.43,4407.78 3454.73,4407.78 3289.43,4573.08 3289.43,5305.98 3314.34,5330.88 3334.24,5310.97 3301.43,5277.88 3301.43,4590.78 3441.43,4450.78 3484.43,4450.78
  region net "": 3484.43,4450.78 3447.04,4450.78 3447.04,4407.78 3484.43,4407.78 3484.43,4408.78 3513.43,4437.78 3513.43,4440.36 3493.01,4460.78 3493.01,4459.36
Board Outline Layer:
  circle w8 net "": c8453.02,6110.18 r62.99
  circle w8 net "": c8453.04,3335.2 r62.99
  circle w8 net "": c4017.97,6110.18 r62.99
  circle w8 net "": c4017.95,3335.5 r62.99
  circle w8 net "": c5613.28,5673.03 r62.99
  circle w8 net "": c5563.28,3773.03 r62.99
  circle w8 net "": c7613.28,5073.03 r62.99
  lines w7.99 net "": 3126.58,6155.44 3127,3290.74 ; 3127.22,6155.18 cw(c3205.96,6155.18) 3205.96,6233.92 ; 3127.26,3290.74 ccw(c3206,3290.74) 3206,3212 ; 3206,3212.04 7199.73,3212.04 7809.93,3212.04 ; 3208.95,6234.03 7199.73,6234.03 7810.42,6234.03 ; 3775.96,3212.04 ccw(c3775.96,3290.78) 3854.7,3290.78 ; 3775.96,6234.18 cw(c3775.96,6155.44) 3854.7,6155.44 3854.7,5838.78 ; 3854.26,5110 3893.78,5110 ; 3854.4,3906.54 3893.91,3906.54 ; 3854.4,4016.02 3893.91,4016.02 ; 3854.4,5033.49 3893.91,5033.49 ; 3854.67,5761.73 3894.18,5761.73 ; 3854.96,3291.04 3854.96,3711.5 3893.95,3711.5 3893.95,3290.99 ccw(c3972.91,3290.99) 3972.91,3212.03 ; 3854.96,3905.78 3854.96,3816.5 3893.95,3816.5 3893.95,3905.78 ; 3854.96,4016.78 3854.96,5032.78 ; 3854.96,5110.78 3854.96,5760.78 ; 3855.53,5837.9 3895.04,5837.9 ; 3893.95,4016.78 3893.95,5032.78 ; 3893.95,5110.78 3893.95,5760.78 ; 3894.22,3290.78 ccw(c3972.96,3290.78) 3972.96,3212.04 ; 3894.21,5838.78 3894.21,6164 ; 3894.21,6155.18 cw(c3972.95,6155.18) 3972.95,6233.92 4111.46,6233.92 ; 3894.21,6155.44 cw(c3972.95,6155.44) 3972.95,6234.18 ; 7687.95,6234.03 8537.67,6234.03 ; 7787.95,3212.04 7868.5,3212.04 8537.67,3212.04 ; 8537.67,6234.24 cw(c8537.67,6155.5) 8616.41,6155.5 8616.41,3675.5 8616.41,3290.18 cw(c8537.67,3290.77) 8537.67,3212.03 ; 8537.67,3212.04 8537.67,3212.03
  lines w10 net "": 3779.96,6234.03 3781.47,6234.02 ccw(c3779.95,6165.32) 3779.96,6234.03 ; 3779.96,6234.03 3779.95,6234.03 ; 3779.95,6234.03 3779.95,6234.03 ; 3779.95,6234.03 3779.96,6234.03 ; 3831.95,3234.5 cw(c3777.74,3288.71) 3777.74,3212.04 3775.96,3212.04 3971.16,3212.04 ; 3831.95,3234.5 3831.95,3234.5 ; 3831.95,3234.5 ccw(c3777.05,3289.4) 3854.7,3289.4 3854.7,3711.36 3894.2,3711.63 3893.78,3291.22 3894.22,3290.78 3894.22,3289.39 ccw(c3971.85,3289.39) 3916.95,3234.5 ccw(c3971.17,3288.71) 3971.16,3212.04 ; 3971.16,3212.04 3971.16,3212.04 ; 3854.26,5110 3854.96,5760.78 3893.95,5760.78 3893.78,5760.61 3893.78,5110 3854.26,5110 ; 3854.96,3816.5 3854.96,3905.78 3893.95,3905.78 3893.95,3816.5 3854.96,3816.5 ; 3854.96,4016.78 3854.96,5032.78 3893.95,5032.78 3893.95,4016.78 3854.96,4016.78 ; 8272.94,4963.39 cw(c8337.85,4963.39) 8337.85,5028.3 cw(c8337.85,4963.39) 8402.76,4963.39 cw(c8337.85,4963.39) 8337.85,4898.49 cw(c8337.85,4963.39) 8272.94,4963.39 ; 8272.94,5413.39 cw(c8337.85,5413.39) 8337.85,5478.3 cw(c8337.85,5413.39) 8402.76,5413.39 cw(c8337.85,5413.39) 8337.85,5348.49 cw(c8337.85,5413.39) 8272.94,5413.39
Multi-Layer:
  region net "": 7853,4849 8665,4849 8665,5553 7853,5553

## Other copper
Top Layer:
  drawing of 805 lines, arcs and shapes, not listed
Bottom Layer:
  drawing of 384 lines, arcs and shapes, not listed

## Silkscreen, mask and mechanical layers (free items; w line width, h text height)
Top Silkscreen Layer:
  drawing of 1279 lines, arcs and shapes, not listed
  text "41" at 5487.58,6135.83 h36
  text "49" at 5082.95,6135.5 h36
  text "31" at 5987.95,6135.5 h36
  text "21" at 6487.95,6135.5 h36
  text "11" at 6992.95,6135.5 h36
  text "1" at 7507.95,6135.5 h36
  text "B10*" at 5186,6038.5 h36 r45
  text "E14" at 5296,6038.5 h36 r45
  text "E12" at 5396,6038.5 h36 r45
  text "E10" at 5496,6038.5 h36 r45
  text "E8" at 5600.95,6038.5 h36 r45
  text "B2" at 5701,6038.5 h36 r45
  text "B0" at 5801,6038.5 h36 r45
  text "A6" at 6001,6038.5 h36 r45
  text "A4" at 6101,6038.5 h36 r45
  text "A2" at 6301,6038.5 h36 r45
  text "A0" at 6401,6038.5 h36 r45
  text "NC" at 6599,6038.5 h36 r45
  text "NC" at 6900.95,6038.5 h36 r45
  text "E6" at 7297.95,6038.5 h36 r45
  text "E4" at 7397.95,6038.5 h36 r45
  text "E2" at 7497.95,6038.5 h36 r45
  text "GND" at 6197.95,6035.5 h36 r45
  text "GND" at 5086,6034 h36 r45
  text "C4" at 5901,6034 h36 r45
  text "C2" at 6701,6034 h36 r45
  text "C0" at 6801,6034 h36 r45
  text "C15" at 7091,6034 h36 r45
  text "C13" at 7191,6034 h36 r45
  text "VDD" at 6991,6030 h36 r45
  text "VREF" at 6492,6027 h36 r45
  text "GND" at 4831.5,5971.97 h48
  text "3V3" at 8133.95,5908.5 h36
  text "USART1_TX" at 7946.8,5809.57 h36
  text "A1" at 6416,5749 h36 r45
  text "C1" at 6810,5749 h36 r45
  text "E9" at 5605,5746 h36 r34.62
  text "A3" at 6311,5741 h36 r45
  text "NC" at 6506,5741 h36 r45
  text "NC" at 6611,5741 h36 r45
  text "C3" at 6711,5741 h36 r45
  text "NC" at 7006,5741 h36 r45
  text "E3" at 7506,5741 h36 r45
  text "E7" at 5711,5736.88 h36 r45
  text "C5" at 5911,5736.82 h36 r45
  text "A7" at 6011,5737 h36 r45
  text "A5" at 6106,5737 h36 r45
  text "E5" at 7411,5737 h36 r45
  text "E11" at 5501,5727.92 h36 r45
  text "B1*" at 5796,5728 h34 r45
  text "NRST" at 6877,5726 h30 r30.83
  text "GND" at 7099,5724 h34 r45
  text "C14" at 7199.73,5723 h36 r45
  text "VBAT" at 7286,5721 h30 r35.07
  text "E13" at 5395.95,5719.58 h36 r45
  text "VDD" at 6201,5719.03 h36 r45
  text "VDD" at 5096,5715 h36 r45
  text "E15" at 5301,5715 h36 r45
  text "USART1_RX" at 7946.8,5709.35 h36
  text "B11*" at 5188,5702 h36 r45
  text "50" at 5082.95,5669.83 h36
  text "VIN (7V-12V)" at 4769.95,5662.5 h48 r90
  text "GND" at 8142.95,5609.5 h36
  text "4" at 7138.58,5563.18 h48 r90
  text "8" at 6677.58,5562.18 h48 r90
  text "7" at 6841.58,5562.18 h48 r90
  text "2" at 7335.58,5562.18 h48 r90
  text "13" at 6175.58,5521.18 h48 r90
  text "12" at 6275.58,5521.18 h48 r90
  text "#6" at 6937.58,5515.18 h48 r90
  text "#5" at 7038.58,5515.18 h48 r90
  text "#9" at 6576.58,5514.18 h48 r90
  text "#3" at 7237.58,5514.18 h48 r90
  text "BOOT1" at 4305.95,5493.5 h48
  text "BOOT0" at 4550.95,5493.5 h48
  text "#11" at 6375.58,5474.18 h48 r90
  text "#10" at 6476.58,5474.18 h48 r90
  text "SCL" at 5775.58,5464.18 h48 r90
  text "SDA" at 5875.58,5464.18 h48 r90
  text "GND" at 6076.28,5464.18 h48 r90
  text "GND" at 4418.95,5432.5 h36
  text "GND" at 4547.95,5432.5 h36
  text "DIGITAL(#=PWM)" at 6525.58,5420.18 h48
  text "TX 1" at 7438.58,5419.18 h48 r90
  text "RX 0" at 7539.58,5419.18 h48 r90
  text "AREF" at 5976.28,5417.18 h48 r90
  text "LD:" at 3774.76,5387.43 h51.92 r270
  text "AT-Link-EZ V1.4" at 3170.01,5275.78 h60 r270
  text "1" at 3776.57,5267 h52.3 r270
  text "2" at 3776.23,5194.39 h52.3 r270
  text "3" at 3775.23,5121.39 h52.3 r270
  text "4" at 3776.23,5046.39 h52.3 r270
  text "VDD" at 4418.95,4997.5 h36
  text "VDD" at 4548.95,4997.5 h36
  text "SPIM" at 4848.95,4953.5 h36
  text "IO*" at 5020.95,4953.5 h36
  text "MISO" at 7286.95,4849.5 h48
  text "5V" at 7705.95,4849.5 h48
  text "IDD" at 4764.58,4784.9 h48 r90
  text "SCK" at 7321.95,4749.5 h48
  text "MOSI" at 7705.95,4749.5 h48
  text "RESET" at 7225.95,4649.5 h48
  text "GND" at 7705.95,4649.5 h48
  text "20-pin ARM standard JTAG" at 4314.95,4605.95 h36 r90
  text "NSS" at 7321.95,4549.5 h48
  text "PB11" at 7545.58,4443.5 h48
  text "POWER" at 6615.84,3994.98 h48
  text "ANALOG IN" at 7133,3994.98 h48
  text "AT-START-A403A" at 5041.89,3897.52 h60
  text "V1.3" at 5977.24,3897.52 h60
  text "AT-Link" at 4128.95,3893.5 h48 r90
  text "IOREF" at 6237.23,3846.18 h48 r90
  text "RESET" at 6335.23,3846.18 h48 r90
  text "3.3V" at 6436.23,3846.18 h48 r90
  text "5V" at 6536.23,3846.18 h48 r90
  text "GND" at 6637.23,3846.18 h48 r90
  text "GND" at 6736.53,3846.18 h48 r90
  text "VIN" at 6836.23,3846.18 h48 r90
  text "AN0" at 7033.23,3846.18 h48 r90
  text "AN1" at 7134.23,3846.18 h48 r90
  text "AN2" at 7234.23,3846.18 h48 r90
  text "AN3" at 7335.23,3846.18 h48 r90
  text "AN4" at 7437.23,3846.18 h48 r90
  text "AN5" at 7537.23,3846.18 h48 r90
  text "SWC" at 3468.43,3793.5 h36 r270
  text "GND" at 3269.95,3792.5 h36 r270
  text "SWD" at 3569.95,3792.5 h36 r270
  text "3V3" at 3669.95,3792.5 h36 r270
  text "NRST" at 3367.95,3789.5 h36 r270
  text "52" at 5082.95,3742.25 h36
  text "68" at 5883.58,3742.25 h36
  text "BOOT0" at 3569.53,3667.5 h36 r270
  text "B13" at 5086,3644 h36 r45
  text "B15" at 5191,3644 h36 r45
  text "D9" at 5301,3644 h36 r45
  text "D11" at 5391,3644 h36 r45
  text "A11" at 5996.45,3644 h36 r45
  text "D1" at 6606,3644 h36 r45
  text "D3" at 6701,3644 h36 r45
  text "D7" at 6906,3644 h36 r45
  text "B4" at 7001,3644 h36 r45
  text "B9" at 7316,3644 h36 r45
  text "E1" at 7401,3644 h36 r45
  text "A9" at 5897.95,3643.5 h36 r45
  text "D5" at 6801,3643.5 h36 r45
  text "C7" at 5706,3641 h36 r45
  text "C9" at 5801,3640 h36 r45
  text "D13" at 5490.95,3639 h30 r45
  text "D15" at 5595.95,3639 h36 r45
  text "A13" at 6090.95,3639 h34 r45
  text "A14" at 6291,3639 h34 r45
  text "B6*" at 7086,3639 h32 r45
  text "BOOT0" at 7156,3637 h30 r24.07
  text "GND" at 6191,3635 h34 r45
  text "C10" at 6391,3634 h36 r45
  text "C12" at 6486,3634 h36 r45
  text "SWO" at 3469.01,3631.5 h36 r270
  text "VDD" at 7498,3629.5 h36 r45
  text "RX" at 3269.53,3609.5 h36 r270
  text "TX" at 3369.53,3609.5 h36 r270
  text "5V" at 3669.53,3609.5 h36 r270
  text "Micro USB" at 8316.95,3468.5 h48 r90
  text "D8" at 5306,3346 h36 r45
  text "C8" at 5806,3346 h36 r45
  text "NC" at 6211,3346 h36 r45
  text "D0" at 6606,3346 h36 r45
  text "D2" at 6706,3346 h36 r45
  text "D4" at 6806,3346 h36 r45
  text "B3" at 7006,3346 h36 r45
  text "B8" at 7306,3346 h36 r45
  text "E0" at 7406,3345.94 h36 r45
  text "C6" at 5706,3342 h36 r45
  text "D6" at 6906,3342 h36 r45
  text "B5" at 7106,3341 h36 r45
  text "C11" at 6501,3333 h36 r45
  text "B14" at 5196,3325 h36 r45
  text "D10" at 5395.95,3325 h36 r45
  text "D12" at 5496,3325 h36 r45
  text "D14" at 5596,3325 h36 r45
  text "A10" at 5995,3325 h36 r45
  text "A12" at 6096,3325 h36 r45
  text "B12" at 5096,3324 h36 r45
  text "A8*" at 5895.95,3321 h36 r45
  text "VDD" at 6296,3321 h36 r45
  text "A15" at 6396,3321 h36 r45
  text "B7*" at 7196,3321 h36 r45
  text "GND" at 7500.95,3321 h36 r45
  text "51" at 5087.95,3270.5 h36
  text "61" at 5588.58,3270.5 h36
  text "71" at 6087.95,3270.5 h36
  text "81" at 6587.95,3270.5 h36
  text "91" at 7089.4,3270.03 h36
  text "100" at 7467.95,3270.03 h36
  text "GND" at 7851.95,3248.5 h48
  text "USER" at 4724.95,3241.5 h48
  text "RESET" at 4329.95,3240.5 h48
Bottom Silkscreen Layer:
  drawing of 290 lines, arcs and shapes, not listed
  text "1" at 7495.85,6034.5 h36 r315
  text "29" at 6103.43,6033.5 h36 r315
  text "27" at 6203.43,6033.5 h36 r315
  text "25" at 6303.43,6033.5 h36 r315
  text "23" at 6403.43,6033.5 h36 r315
  text "21" at 6503.43,6033.5 h36 r315
  text "NC" at 6603.43,6033.5 h36 r315
  text "17" at 6698.43,6033.5 h36 r315
  text "15" at 6798.43,6033.5 h36 r315
  text "NC" at 6903.43,6033.5 h36 r315
  text "11" at 6998.43,6033.5 h36 r315
  text "7" at 7195.85,6033.5 h36 r315
  text "39" at 5603.43,6029.5 h36 r315
  text "37" at 5703.43,6029.5 h36 r315
  text "35" at 5803.43,6029.5 h36 r315
  text "33" at 5903.43,6029.5 h36 r315
  text "31" at 6003.43,6029.5 h36 r315
  text "9" at 7095.85,6029.5 h36 r315
  text "5" at 7295.85,6029.5 h36 r315
  text "3" at 7395.85,6029.5 h36 r315
  text "49" at 5106.43,6026.5 h36 r315
  text "47" at 5206.43,6026.5 h36 r315
  text "45" at 5306.43,6026.5 h36 r315
  text "43" at 5406.43,6026.5 h36 r315
  text "41" at 5506.43,6026.5 h36 r315
  text "8" at 7195.85,5773.5 h36 r315
  text "2" at 7495.85,5773.5 h36 r315
  text "6" at 7295.85,5769.5 h36 r315
  text "4" at 7393,5767.5 h42 r315
  text "50" at 5098.43,5749.5 h36 r315
  text "28" at 6203.43,5748.5 h36 r315
  text "26" at 6303.43,5748.5 h36 r315
  text "24" at 6403.43,5748.5 h36 r315
  text "NC" at 6503.43,5748.5 h36 r315
  text "NC" at 6603.43,5748.5 h36 r315
  text "18" at 6698.43,5748.5 h36 r315
  text "16" at 6798.43,5748.5 h36 r315
  text "14" at 6898.43,5748.5 h36 r315
  text "NC" at 7003.43,5748.5 h36 r315
  text "10" at 7098.43,5748.5 h36 r315
  text "38" at 5703.43,5744.5 h36 r315
  text "36" at 5803.43,5744.5 h36 r315
  text "34" at 5903.43,5744.5 h36 r315
  text "32" at 6003.43,5744.5 h36 r315
  text "30" at 6103.43,5744.5 h36 r315
  text "48" at 5206.43,5741.5 h36 r315
  text "46" at 5306.43,5741.5 h36 r315
  text "44" at 5406.43,5741.5 h36 r315
  text "42" at 5506.43,5741.5 h36 r315
  text "40" at 5606.43,5741.5 h36 r315
  text "3V3" at 4271.39,5457.92 h36
  text "3V3" at 4413.36,5457.92 h36
  text "NJTRST" at 4356.46,5367.32 h36
  text "GND" at 4488.94,5367.32 h36
  text "AT32A403AVGT7" at 6892.66,5355.5 h120
  text "JTDI" at 4290.64,5260.78 h36
  text "GND" at 4413.46,5260.52 h36
  text "JTMS" at 4290.64,5162.5 h36
  text "GND" at 4413.1,5162.49 h36
  text "JTCK" at 4290.64,5062.5 h36
  text "GND" at 4412.74,5062.49 h36
  text "NC" at 4274.56,4962.49 h36
  text "GND" at 4413.1,4962.49 h36
  text "JTDO" at 4290.64,4859.5 h36
  text "GND" at 4413.46,4859.49 h36
  text "VDD" at 3645.69,4847.93 h36 r270
  text "GND" at 4413.36,4765.83 h36
  text "NRST" at 4290.64,4765.5 h36
  text "NC" at 4274.56,4662.49 h36
  text "GND" at 4412.74,4662.49 h36
  text "NC" at 4274.56,4560.49 h36
  text "GND" at 4413.36,4560.49 h36
  text "VDD" at 3663.47,4390.86 h36
  text "M-SWDIO" at 3651.16,4313.5 h36
  text "3V3" at 4205.81,4225.5 h36
  text "E5V" at 4528.81,4225.5 h36
  text "M-SWCLK" at 3651.16,4213.5 h36
  text "SWDIO" at 4199.48,4125.5 h36
  text "BOOT0" at 4594.44,4125.18 h36
  text "M-NRST" at 3654.32,4113.5 h36
  text "SWCLK" at 4199.48,4025.5 h36
  text "SWO" at 4528.81,4024.5 h36
  text "GND" at 3663.81,4013.5 h36
  text "NRST" at 4202.64,3925.5 h36
  text "USART1_RX" at 4715.84,3924.5 h36
  text "GND" at 4205.81,3825.5 h36
  text "USART1_TX" at 4716.84,3821.5 h36
  text "70" at 6000.43,3633.5 h36 r315
  text "72" at 6100.43,3633.5 h36 r315
  text "74" at 6200.43,3633.5 h36 r315
  text "76" at 6300.43,3633.5 h36 r315
  text "78" at 6400.43,3633.5 h36 r315
  text "52" at 5100.43,3629.18 h36 r315
  text "54" at 5200.43,3629.18 h36 r315
  text "56" at 5300.43,3629.18 h36 r315
  text "58" at 5400.43,3629.18 h36 r315
  text "60" at 5506.43,3629.18 h36 r315
  text "62" at 5606.75,3629.18 h36 r315
  text "64" at 5710.05,3629.18 h36 r315
  text "66" at 5806.43,3629.18 h36 r315
  text "68" at 5906.43,3629.18 h36 r315
  text "80" at 6503.43,3629.18 h36 r315
  text "82" at 6603.43,3629.18 h36 r315
  text "84" at 6703.43,3629.18 h36 r315
  text "86" at 6803.43,3629.18 h36 r315
  text "88" at 6903.43,3629.18 h36 r315
  text "90" at 7001.43,3629.18 h36 r315
  text "92" at 7101.43,3629.18 h36 r315
  text "94" at 7201.43,3629.18 h36 r315
  text "96" at 7301.43,3629.18 h36 r315
  text "98" at 7401.43,3629.18 h36 r315
  text "100" at 7514.53,3623.5 h36 r315
  text "71" at 6100.43,3348.5 h36 r315
  text "NC" at 6203.43,3348.5 h36 r315
  text "75" at 6300.43,3348.5 h36 r315
  text "77" at 6400.43,3348.5 h36 r315
  text "79" at 6500.43,3348.5 h36 r315
  text "51" at 5100.43,3346.5 h36 r315
  text "53" at 5200.43,3344.5 h36 r315
  text "55" at 5300.43,3344.5 h36 r315
  text "57" at 5400.43,3344.5 h36 r315
  text "59" at 5500.43,3344.5 h36 r315
  text "61" at 5606.75,3344.5 h36 r315
  text "63" at 5701.43,3344.5 h36 r315
  text "65" at 5806.43,3344.5 h36 r315
  text "67" at 5906.43,3344.5 h36 r315
  text "69" at 6006.43,3344.5 h36 r315
  text "81" at 6603.43,3344.5 h36 r315
  text "83" at 6703.43,3344.5 h36 r315
  text "85" at 6803.43,3344.5 h36 r315
  text "87" at 6903.43,3344.5 h36 r315
  text "89" at 7003.43,3344.5 h36 r315
  text "91" at 7101.43,3344.5 h36 r315
  text "93" at 7201.43,3344.5 h36 r315
  text "95" at 7301.43,3344.5 h36 r315
  text "97" at 7401.43,3344.5 h36 r315
  text "99" at 7501.43,3344.5 h36 r315
Mechanical Layer:
  lines w1 net "": 3952.66,3335.33 ccw(c4017.66,3335.33) 4017.66,3270.33 ccw(c4017.66,3333.33) 4080.65,3333.33 4080.65,3337.34 ccw(c4017.66,3337.34) 4017.66,3400.33 4012.66,3400.33 ccw(c4012.66,3340.33) 3952.66,3340.33 3952.66,3335.33 ; 3952.66,6110.33 ccw(c4017.66,6110.33) 4017.66,6045.33 ccw(c4017.66,6108.33) 4080.65,6108.33 4080.65,6112.34 ccw(c4017.66,6112.34) 4017.66,6175.33 4012.66,6175.33 ccw(c4012.66,6115.33) 3952.66,6115.33 3952.66,6110.33 ; 5498.28,3773.03 ccw(c5563.28,3773.03) 5563.28,3708.03 ccw(c5563.28,3771.03) 5626.27,3771.03 5626.27,3775.04 ccw(c5563.28,3775.04) 5563.28,3838.03 5558.28,3838.03 ccw(c5558.28,3778.03) 5498.28,3778.03 5498.28,3773.03 ; 5548.28,5673.03 ccw(c5613.28,5673.03) 5613.28,5608.03 ccw(c5613.28,5671.03) 5676.27,5671.03 5676.27,5675.04 ccw(c5613.28,5675.04) 5613.28,5738.03 5608.28,5738.03 ccw(c5608.28,5678.03) 5548.28,5678.03 5548.28,5673.03 ; 7548.28,5073.03 ccw(c7613.28,5073.03) 7613.28,5008.03 ccw(c7613.28,5071.03) 7676.27,5071.03 7676.27,5075.04 ccw(c7613.28,5075.04) 7613.28,5138.03 7608.28,5138.03 ccw(c7608.28,5078.03) 7548.28,5078.03 7548.28,5073.03 ; 8388.43,3335.03 ccw(c8453.43,3335.03) 8453.43,3270.03 ccw(c8453.43,3333.03) 8516.42,3333.03 8516.42,3337.04 ccw(c8453.43,3337.04) 8453.43,3400.03 8448.43,3400.03 ccw(c8448.43,3340.03) 8388.43,3340.03 8388.43,3335.03 ; 8389.28,6109.65 ccw(c8454.28,6109.65) 8454.28,6044.65 ccw(c8454.28,6107.65) 8517.27,6107.65 8517.27,6111.66 ccw(c8454.28,6111.66) 8454.28,6174.65 8449.28,6174.65 ccw(c8449.28,6114.65) 8389.28,6114.65 8389.28,6109.65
